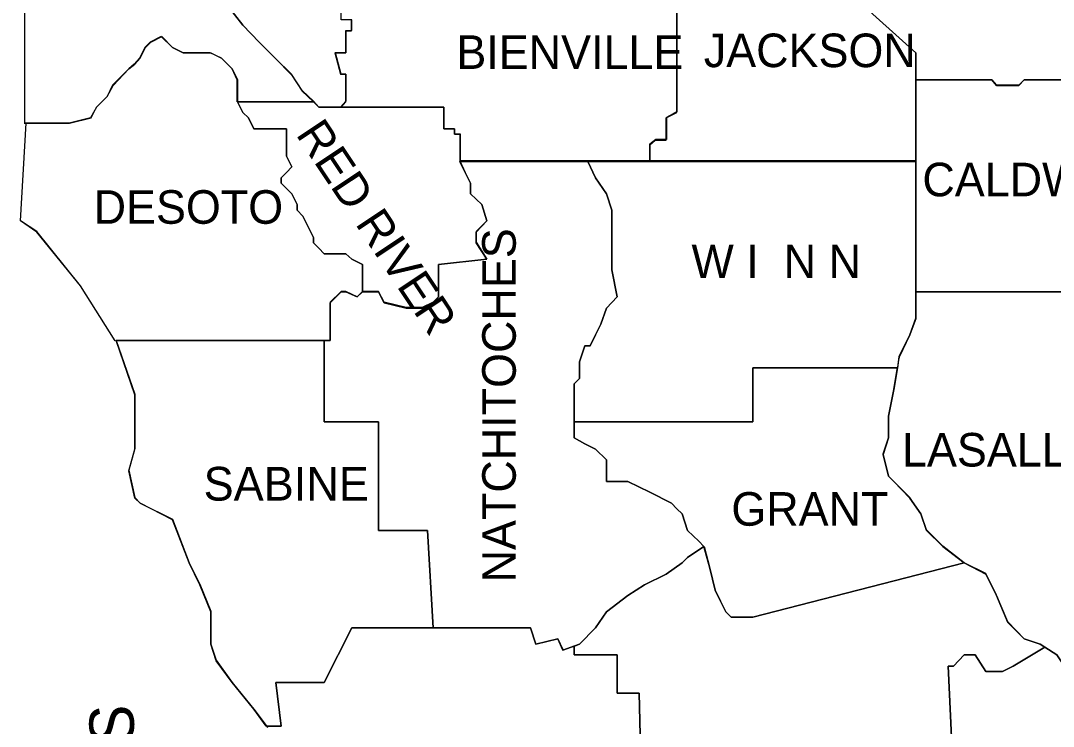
# Model space of a CAD drawing. Extents: x 0.23 to 2.82, y 0.04 to 1.79.
# Drawn here: x 2.2153 to 2.3593, y 1.594 to 1.6923 of the extents above; entities that cross this region are included whole.
import ezdxf

# ---------------------------------------------------------------- set-up
doc = ezdxf.new("R2010")
doc.units = 0
for name, color, linetype in [('Dist04', 7, 'Continuous'), ('Dist05', 7, 'Continuous'), ('Dist08', 7, 'Continuous'), ('Dist58', 7, 'Continuous'), ('Standard Info', 7, 'Continuous')]:
    doc.layers.add(name, color=color, linetype=linetype)

msp = doc.modelspace()

# ---------------------------------------------------------------- linework, layer by layer
at = {"layer": 'Dist04'}
for p, q in [((2.2159, 1.678), (2.2159, 1.75058)), ((2.21532, 1.66442), (2.21607, 1.678)), ((2.21607, 1.678), (2.2159, 1.678))]:
    msp.add_line(p, q, dxfattribs=at)
for points in [[(2.30682, 1.6985), (2.30682, 1.67958), (2.3054, 1.67883), (2.3054, 1.6765), (2.3054, 1.67575), (2.3039, 1.67575), (2.30307, 1.67508), (2.30307, 1.67275)], [(2.27657, 1.67275), (2.27732, 1.67117), (2.27807, 1.66967), (2.27807, 1.66817), (2.27965, 1.66667), (2.28032, 1.66442), (2.27882, 1.66292), (2.27882, 1.66142), (2.28032, 1.65908), (2.27357, 1.65833), (2.27357, 1.65383), (2.27282, 1.65308), (2.27132, 1.65233), (2.26907, 1.65233), (2.26599, 1.65308), (2.26524, 1.65458), (2.26299, 1.65458)], [(2.30307, 1.67275), (2.27665, 1.67275)], [(2.22849, 1.64767), (2.22365, 1.65533), (2.21757, 1.66292), (2.21532, 1.66442)], [(2.26299, 1.65458), (2.26224, 1.65383), (2.26065, 1.65458), (2.25999, 1.65458), (2.25849, 1.65308), (2.25849, 1.64775), (2.25765, 1.64775)], [(2.25765, 1.64775), (2.22865, 1.64775)]]:
    msp.add_lwpolyline(points, dxfattribs=at)
at = {"layer": 'Dist05'}
for points in [[(2.30307, 1.67275), (2.30307, 1.67508), (2.3039, 1.67575), (2.3054, 1.67575), (2.3054, 1.6765), (2.3054, 1.67883), (2.30682, 1.67958), (2.30682, 1.6985)], [(2.36049, 1.68408), (2.35524, 1.68408), (2.35449, 1.68333), (2.3514, 1.68333), (2.35074, 1.68408), (2.34015, 1.68408)], [(2.34015, 1.684), (2.34015, 1.67275)], [(2.34015, 1.67275), (2.30307, 1.67275)]]:
    msp.add_lwpolyline(points, dxfattribs=at)
at = {"layer": 'Dist08'}
for points in [[(2.27657, 1.67275), (2.27732, 1.67117), (2.27807, 1.66967), (2.27807, 1.66817), (2.27965, 1.66667), (2.28032, 1.66442), (2.27882, 1.66292), (2.27882, 1.66142), (2.28032, 1.65908), (2.27357, 1.65833), (2.27357, 1.65383), (2.27282, 1.65308), (2.27132, 1.65233), (2.26907, 1.65233), (2.26599, 1.65308), (2.26524, 1.65458), (2.26299, 1.65458)], [(2.30307, 1.67275), (2.27665, 1.67275)], [(2.34015, 1.67275), (2.30307, 1.67275)], [(2.34015, 1.65458), (2.34015, 1.67275)], [(2.26299, 1.65458), (2.26224, 1.65383), (2.26065, 1.65458), (2.25999, 1.65458), (2.25849, 1.65308), (2.25849, 1.64775), (2.25765, 1.64775)], [(2.33765, 1.644), (2.33782, 1.6455), (2.33932, 1.6485), (2.34015, 1.65083), (2.34015, 1.65458)], [(2.22865, 1.64775), (2.23124, 1.64025), (2.23124, 1.63267), (2.2304, 1.62967), (2.23124, 1.62583), (2.23199, 1.62508), (2.23649, 1.62283), (2.23882, 1.61675), (2.24032, 1.61375), (2.24182, 1.61), (2.24182, 1.60542), (2.24257, 1.60317), (2.24482, 1.60008), (2.24782, 1.59633), (2.24957, 1.59408)], [(2.25765, 1.64775), (2.22865, 1.64775)], [(2.36207, 1.60008), (2.36132, 1.60167), (2.35982, 1.60392), (2.35749, 1.60542), (2.35524, 1.60617), (2.35299, 1.6085), (2.3514, 1.61225), (2.3499, 1.61525), (2.3469, 1.61675), (2.3439, 1.61908), (2.34165, 1.62133), (2.34082, 1.62358), (2.33932, 1.62583), (2.33707, 1.62808), (2.33632, 1.62883), (2.33557, 1.63192), (2.33632, 1.63417), (2.33632, 1.63717), (2.33707, 1.64092), (2.33757, 1.644)]]:
    msp.add_lwpolyline(points, dxfattribs=at)
at = {"layer": 'Dist58'}
for points in [[(2.34015, 1.68408), (2.35074, 1.68408), (2.3514, 1.68333), (2.35449, 1.68333), (2.35524, 1.68408), (2.36049, 1.68408)], [(2.34015, 1.67275), (2.34015, 1.684)], [(2.34015, 1.65458), (2.34015, 1.67275)], [(2.33765, 1.644), (2.33782, 1.6455), (2.33932, 1.6485), (2.34015, 1.65083), (2.34015, 1.65458)], [(2.36207, 1.60008), (2.36132, 1.60167), (2.35982, 1.60392), (2.35749, 1.60542), (2.35524, 1.60617), (2.35299, 1.6085), (2.3514, 1.61225), (2.3499, 1.61525), (2.3469, 1.61675), (2.3439, 1.61908), (2.34165, 1.62133), (2.34082, 1.62358), (2.33932, 1.62583), (2.33707, 1.62808), (2.33632, 1.62883), (2.33557, 1.63192), (2.33632, 1.63417), (2.33632, 1.63717), (2.33707, 1.64092), (2.33757, 1.644)]]:
    msp.add_lwpolyline(points, dxfattribs=at)
at = {"layer": 'Standard Info'}
for p, q in [((2.2159, 1.67792), (2.2159, 1.75058)), ((2.24557, 1.681), (2.25615, 1.681)), ((2.2569, 1.68025), (2.25615, 1.68108)), ((2.2599, 1.68025), (2.2569, 1.68025)), ((2.21532, 1.66442), (2.21607, 1.678)), ((2.22865, 1.64775), (2.22849, 1.64767)), ((2.33774, 1.645), (2.33757, 1.64392)), ((2.2909, 1.60458), (2.29249, 1.60517)), ((2.29249, 1.60517), (2.29265, 1.60517)), ((2.2499, 1.594), (2.24957, 1.594)), ((2.24965, 1.59383), (2.2499, 1.594))]:
    msp.add_line(p, q, dxfattribs=at)
for points in [[(2.25615, 1.68108), (2.25457, 1.68258), (2.25307, 1.68483), (2.25082, 1.68708), (2.24857, 1.68933), (2.24632, 1.69167), (2.24399, 1.69467), (2.23949, 1.69925), (2.23649, 1.70442), (2.23574, 1.70825), (2.2349, 1.71433), (2.23424, 1.71958), (2.2334, 1.72342), (2.2334, 1.72717), (2.23424, 1.72942), (2.2334, 1.7325), (2.23265, 1.73317), (2.23199, 1.7355), (2.23199, 1.73775), (2.23199, 1.74067), (2.23124, 1.743), (2.2334, 1.75058)], [(2.34015, 1.68408), (2.34015, 1.68783), (2.33182, 1.69533), (2.33182, 1.70292), (2.33182, 1.70975)], [(2.33182, 1.70292), (2.33182, 1.69533), (2.34015, 1.68783), (2.34015, 1.68408)], [(2.30682, 1.6985), (2.30682, 1.67958), (2.3054, 1.67875), (2.3054, 1.6765), (2.3054, 1.67575), (2.3039, 1.67575), (2.30307, 1.675), (2.30307, 1.67267)], [(2.30307, 1.67267), (2.30307, 1.675), (2.30382, 1.67567), (2.30532, 1.67567), (2.30532, 1.6765), (2.30532, 1.67875), (2.30682, 1.6795), (2.30682, 1.69842)], [(2.25999, 1.68025), (2.26065, 1.681), (2.26065, 1.68183), (2.26065, 1.68333), (2.26065, 1.68483), (2.25999, 1.68483), (2.25924, 1.68783), (2.26065, 1.68783), (2.26065, 1.69092), (2.26149, 1.69092), (2.26149, 1.69242), (2.25999, 1.69242), (2.25999, 1.69467), (2.26299, 1.69467), (2.26299, 1.69542)], [(2.24399, 1.69467), (2.24632, 1.69167), (2.24857, 1.68933), (2.25082, 1.68708), (2.25307, 1.68475), (2.25457, 1.6825), (2.25615, 1.681), (2.24549, 1.681), (2.24549, 1.68175), (2.24549, 1.68408), (2.24482, 1.68558), (2.24332, 1.68708), (2.24174, 1.68783), (2.23949, 1.68783), (2.23799, 1.68783), (2.23649, 1.68858), (2.2349, 1.69008), (2.2349, 1.69008), (2.2334, 1.68933), (2.23265, 1.68858), (2.2319, 1.68708), (2.23115, 1.68625), (2.2304, 1.68558), (2.22815, 1.68333), (2.2274, 1.68175), (2.2259, 1.68025), (2.22507, 1.67875), (2.22207, 1.678), (2.21982, 1.678), (2.21607, 1.678)], [(2.2614, 1.69233), (2.2614, 1.69083), (2.26065, 1.69083), (2.26065, 1.68783), (2.25915, 1.68783), (2.2599, 1.68483), (2.26065, 1.68483), (2.26065, 1.68333), (2.26065, 1.68183), (2.26065, 1.68108), (2.2599, 1.68025)], [(2.21607, 1.678), (2.21982, 1.678), (2.22215, 1.678), (2.22515, 1.67875), (2.2259, 1.68025), (2.2274, 1.68175), (2.22824, 1.68325), (2.2304, 1.68558), (2.23124, 1.68625), (2.23199, 1.68708), (2.23274, 1.68858), (2.23349, 1.68933), (2.23499, 1.69008), (2.23499, 1.69008), (2.23649, 1.68858), (2.23799, 1.68783), (2.23949, 1.68783), (2.24182, 1.68783), (2.24332, 1.68708), (2.24482, 1.68558), (2.24557, 1.68408), (2.24557, 1.68175), (2.24557, 1.681)], [(2.36049, 1.68408), (2.35524, 1.68408), (2.35449, 1.68325), (2.3514, 1.68325), (2.35074, 1.68408), (2.34015, 1.68408)], [(2.34015, 1.68408), (2.35074, 1.68408), (2.3514, 1.68325), (2.35449, 1.68325), (2.35524, 1.68408), (2.36282, 1.68408), (2.36282, 1.68325), (2.36207, 1.681), (2.36282, 1.68025), (2.36282, 1.67875), (2.36357, 1.678), (2.36432, 1.6765), (2.36507, 1.67567), (2.36657, 1.675), (2.36807, 1.675), (2.36957, 1.675)], [(2.34015, 1.68392), (2.34015, 1.67267)], [(2.34015, 1.67267), (2.34015, 1.68383)], [(2.24557, 1.681), (2.24632, 1.6795), (2.24707, 1.67875), (2.24782, 1.67725), (2.2524, 1.67725), (2.2524, 1.67342), (2.25315, 1.67192), (2.2524, 1.67117), (2.25165, 1.67042), (2.25165, 1.66967), (2.2524, 1.66892), (2.25315, 1.66817), (2.2539, 1.66667), (2.2539, 1.66592), (2.25465, 1.66508), (2.2554, 1.66358), (2.25615, 1.66208), (2.25615, 1.66133), (2.2569, 1.66058), (2.25765, 1.65983), (2.25915, 1.65983), (2.26065, 1.65983), (2.26149, 1.65908), (2.26299, 1.65833), (2.26299, 1.6545)], [(2.26299, 1.6545), (2.26299, 1.65833), (2.26149, 1.65908), (2.26065, 1.65983), (2.25915, 1.65983), (2.25765, 1.65983), (2.2569, 1.66058), (2.25615, 1.66133), (2.25615, 1.66208), (2.2554, 1.66358), (2.25465, 1.66508), (2.2539, 1.66592), (2.2539, 1.66667), (2.25315, 1.66817), (2.2524, 1.66892), (2.25165, 1.66967), (2.25165, 1.67042), (2.2524, 1.67117), (2.25315, 1.67192), (2.2524, 1.67342), (2.2524, 1.67725), (2.24782, 1.67725), (2.24707, 1.67875), (2.24632, 1.6795), (2.24557, 1.681)], [(2.25615, 1.681), (2.2569, 1.68025), (2.27432, 1.68025), (2.27432, 1.67725), (2.27582, 1.67725), (2.27582, 1.6765), (2.27657, 1.6765), (2.27657, 1.67267)], [(2.27665, 1.67267), (2.27665, 1.6765), (2.27582, 1.6765), (2.27582, 1.67725), (2.27432, 1.67725), (2.27432, 1.68025), (2.25999, 1.68025)], [(2.25765, 1.64775), (2.25849, 1.64775), (2.25849, 1.653), (2.25999, 1.6545), (2.26065, 1.6545), (2.26224, 1.65383), (2.26299, 1.6545), (2.26524, 1.6545), (2.26599, 1.653), (2.26907, 1.65225), (2.27132, 1.65225), (2.27282, 1.653), (2.27357, 1.65383), (2.27357, 1.65833), (2.28032, 1.65908), (2.27882, 1.66133), (2.27882, 1.66283), (2.28032, 1.66442), (2.27965, 1.66667), (2.27807, 1.66817), (2.27807, 1.66967), (2.27732, 1.67117), (2.27657, 1.67267)], [(2.27657, 1.67267), (2.27732, 1.67117), (2.27807, 1.66967), (2.27807, 1.66817), (2.27965, 1.66667), (2.28032, 1.66442), (2.27882, 1.66283), (2.27882, 1.66133), (2.28032, 1.65908), (2.27357, 1.65833), (2.27357, 1.65383), (2.27282, 1.653), (2.27132, 1.65225), (2.26907, 1.65225), (2.26599, 1.653), (2.26524, 1.6545), (2.26299, 1.6545)], [(2.27657, 1.67267), (2.2944, 1.67267)], [(2.30307, 1.67267), (2.27665, 1.67267)], [(2.29249, 1.63642), (2.29249, 1.64167), (2.29324, 1.64242), (2.29324, 1.64317), (2.29324, 1.64475), (2.29399, 1.647), (2.29474, 1.647), (2.29549, 1.6485), (2.29624, 1.65), (2.29699, 1.65225), (2.29849, 1.65383), (2.29774, 1.65758), (2.29774, 1.66133), (2.29774, 1.66358), (2.29774, 1.66592), (2.29699, 1.66817), (2.29549, 1.67042), (2.2944, 1.67267)], [(2.2944, 1.67267), (2.29549, 1.67042), (2.29699, 1.66817), (2.29774, 1.66592), (2.29774, 1.66358), (2.29774, 1.66133), (2.29774, 1.65758), (2.29849, 1.65383), (2.29699, 1.65225), (2.29624, 1.65), (2.29549, 1.6485), (2.29474, 1.647), (2.29399, 1.647), (2.29324, 1.64475), (2.29324, 1.64317), (2.29324, 1.64242), (2.29249, 1.64167), (2.29249, 1.63417), (2.29399, 1.63333), (2.29549, 1.63258), (2.29699, 1.63108), (2.29699, 1.63033), (2.29699, 1.62808), (2.29999, 1.62808), (2.30307, 1.62658), (2.30607, 1.62508), (2.30682, 1.62425), (2.30757, 1.62358), (2.30832, 1.62125), (2.3099, 1.61975), (2.31057, 1.619)], [(2.2944, 1.67267), (2.34015, 1.67267)], [(2.34015, 1.67267), (2.30307, 1.67267)], [(2.34015, 1.67267), (2.34015, 1.65075), (2.33932, 1.6485), (2.33782, 1.64542), (2.33774, 1.645)], [(2.34015, 1.6545), (2.34015, 1.67267)], [(2.22849, 1.64767), (2.22365, 1.65533), (2.21757, 1.66283), (2.21532, 1.66442)], [(2.3704, 1.65833), (2.36807, 1.65833), (2.36882, 1.6545), (2.36207, 1.6545), (2.34015, 1.6545)], [(2.26299, 1.6545), (2.26224, 1.65383), (2.26065, 1.6545), (2.25999, 1.6545), (2.25849, 1.653), (2.25849, 1.64775), (2.25765, 1.64775)], [(2.33765, 1.64392), (2.33782, 1.64542), (2.33932, 1.6485), (2.34015, 1.65075), (2.34015, 1.6545)], [(2.34015, 1.6545), (2.36207, 1.6545)], [(2.25765, 1.64775), (2.22865, 1.64775)], [(2.24957, 1.594), (2.24782, 1.59633), (2.24482, 1.60008), (2.24257, 1.60308), (2.24182, 1.60542), (2.24182, 1.60992), (2.24032, 1.61367), (2.23882, 1.61675), (2.23649, 1.62275), (2.23199, 1.62508), (2.23124, 1.62575), (2.2304, 1.62958), (2.23124, 1.63258), (2.23124, 1.64017), (2.22865, 1.64775)], [(2.22865, 1.64775), (2.25765, 1.64775)], [(2.25765, 1.64775), (2.25765, 1.63642), (2.26524, 1.63642), (2.26524, 1.62125), (2.27207, 1.62125), (2.27282, 1.60767)], [(2.27282, 1.60767), (2.27207, 1.62125), (2.26524, 1.62125), (2.26524, 1.63642), (2.25765, 1.63642), (2.25765, 1.64775)], [(2.33757, 1.64392), (2.3174, 1.64392), (2.3174, 1.63642), (2.29699, 1.63642), (2.29249, 1.63642)], [(2.29249, 1.63642), (2.29699, 1.63642), (2.3174, 1.63642), (2.3174, 1.64392), (2.33757, 1.64392)], [(2.36207, 1.60008), (2.36132, 1.60158), (2.35982, 1.60392), (2.35749, 1.60542), (2.35524, 1.60617), (2.35299, 1.60842), (2.3514, 1.61217), (2.3499, 1.61517), (2.3469, 1.61675), (2.3439, 1.619), (2.34165, 1.62125), (2.34082, 1.62358), (2.33932, 1.62575), (2.33707, 1.62808), (2.33632, 1.62883), (2.33557, 1.63183), (2.33632, 1.63417), (2.33632, 1.63717), (2.33707, 1.64092), (2.33757, 1.64392)], [(2.33757, 1.64392), (2.33707, 1.64092), (2.33632, 1.63717), (2.33632, 1.63417), (2.33557, 1.63183), (2.33632, 1.62883), (2.33707, 1.62808), (2.33932, 1.62575), (2.34082, 1.62358), (2.34165, 1.62125), (2.3439, 1.619), (2.3469, 1.61675)], [(2.3469, 1.61675), (2.3174, 1.60917), (2.3144, 1.60917), (2.31365, 1.60992), (2.3129, 1.61142), (2.31215, 1.61292), (2.3114, 1.616), (2.31057, 1.619), (2.3099, 1.61975), (2.30832, 1.62125), (2.30757, 1.62358), (2.30682, 1.62425), (2.30607, 1.62508), (2.30307, 1.62658), (2.29999, 1.62808), (2.29699, 1.62808), (2.29699, 1.63033), (2.29699, 1.63108), (2.29549, 1.63258), (2.29399, 1.63333), (2.29249, 1.63417), (2.29249, 1.63642)], [(2.31057, 1.619), (2.30832, 1.6175), (2.30757, 1.61675), (2.30532, 1.61517), (2.30232, 1.61367), (2.29999, 1.61217), (2.29699, 1.60992), (2.29549, 1.60767), (2.29324, 1.60542), (2.2909, 1.60458)], [(2.2909, 1.60458), (2.29324, 1.60542), (2.29549, 1.60767), (2.29699, 1.60992), (2.29999, 1.61217), (2.30232, 1.61367), (2.30532, 1.61517), (2.30757, 1.61675), (2.30832, 1.6175), (2.31057, 1.619)], [(2.29265, 1.60517), (2.29324, 1.60542), (2.29549, 1.60767), (2.29699, 1.60992), (2.29999, 1.61217), (2.30232, 1.61367), (2.30532, 1.61517), (2.30757, 1.61675), (2.30832, 1.6175), (2.31057, 1.619)], [(2.31065, 1.619), (2.3114, 1.616), (2.31215, 1.61292), (2.3129, 1.61142), (2.31365, 1.60992), (2.3144, 1.60917), (2.3174, 1.60917), (2.3469, 1.61675)], [(2.3469, 1.61675), (2.3499, 1.61517), (2.3514, 1.61217), (2.35299, 1.60842), (2.35524, 1.60617), (2.35749, 1.60542), (2.35815, 1.605)], [(2.27282, 1.60767), (2.26149, 1.60767), (2.25765, 1.60008), (2.2509, 1.60008), (2.25165, 1.594), (2.2499, 1.594)], [(2.2499, 1.594), (2.25165, 1.594), (2.2509, 1.60008), (2.25765, 1.60008), (2.26149, 1.60767), (2.2864, 1.60767), (2.28715, 1.60542), (2.29024, 1.60617), (2.2909, 1.60458)], [(2.2499, 1.594), (2.25165, 1.594), (2.2509, 1.60008), (2.25765, 1.60008), (2.26149, 1.60767), (2.2864, 1.60767), (2.28715, 1.60542), (2.29024, 1.60617), (2.2909, 1.60467)], [(2.2909, 1.60458), (2.29024, 1.60617), (2.28715, 1.60542), (2.2864, 1.60767), (2.27282, 1.60767)], [(2.29249, 1.60517), (2.29249, 1.60392), (2.29849, 1.60392), (2.29849, 1.59858), (2.30157, 1.59858), (2.30232, 1.56758)], [(2.29249, 1.60517), (2.29249, 1.60392), (2.29849, 1.60392), (2.29849, 1.59858), (2.30157, 1.59858), (2.30232, 1.56758)], [(2.30232, 1.56758), (2.30157, 1.59858), (2.29849, 1.59858), (2.29849, 1.60392), (2.29249, 1.60392), (2.29249, 1.60517)], [(2.29249, 1.60508), (2.29249, 1.60392), (2.29849, 1.60392), (2.29849, 1.59858), (2.30157, 1.59858), (2.30232, 1.56758)], [(2.35815, 1.605), (2.35374, 1.60233), (2.35224, 1.60158), (2.35074, 1.60158), (2.3499, 1.60158), (2.3484, 1.60392), (2.3469, 1.60392), (2.3454, 1.60233), (2.34465, 1.60233), (2.3454, 1.5865), (2.34615, 1.57967), (2.3484, 1.57283), (2.3424, 1.57283)], [(2.3424, 1.57283), (2.3484, 1.57283), (2.34615, 1.57967), (2.3454, 1.5865), (2.34465, 1.60233), (2.3454, 1.60233), (2.3469, 1.60392), (2.3484, 1.60392), (2.3499, 1.60158), (2.35074, 1.60158), (2.35224, 1.60158), (2.35374, 1.60233), (2.35815, 1.605)], [(2.35815, 1.605), (2.35982, 1.60392), (2.36132, 1.60158), (2.36207, 1.60008), (2.36357, 1.59858), (2.36432, 1.59708), (2.36582, 1.59633), (2.36732, 1.59783), (2.36657, 1.59933), (2.36807, 1.60083), (2.3719, 1.60083), (2.37415, 1.59783), (2.3764, 1.5955), (2.38015, 1.594), (2.38249, 1.594), (2.38399, 1.59333), (2.38549, 1.59175), (2.38474, 1.5895), (2.38399, 1.5865), (2.38399, 1.58342), (2.38249, 1.58192), (2.38065, 1.57833)]]:
    msp.add_lwpolyline(points, dxfattribs=at)

# ---------------------------------------------------------------- texts
for s, height, p in [('JACKSON', 0.004679, (2.31058, 1.68583)), ('BIENVILLE', 0.004679, (2.27608, 1.68558)), ('CALDWELL', 0.004679, (2.34106, 1.66783)), ('DESOTO', 0.004679, (2.2255, 1.664)), ('W I  N N', 0.004679, (2.30886, 1.65642)), ('LASALLE', 0.004679, (2.33822, 1.63017)), ('SABINE', 0.0047, (2.24083, 1.62542)), ('GRANT', 0.004679, (2.31442, 1.62192))]:
    msp.add_text(s, height=height, dxfattribs=at).set_placement(p)
for s, height, rotation, p in [('RED RIVER', 0.004679, 303.6501, (2.2536, 1.67647)), ('NATCHITOCHES', 0.004679, 90, (2.28436, 1.61401)), ('T E X A S', 0.0062, 90, (2.23111, 1.56058))]:
    msp.add_text(s, height=height, rotation=rotation, dxfattribs=at).set_placement(p)

doc.saveas('drawing.dxf')
